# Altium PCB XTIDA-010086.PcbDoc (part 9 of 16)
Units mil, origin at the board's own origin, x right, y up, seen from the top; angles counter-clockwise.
Board outline 14763.78 x 8267.72 mil, 6 copper layers (Top Layer, GND Layer, Signal Layer 1, Signal Layer 2, Power Layer, Bottom Layer), stack 62 mil thick; 1933 components, 1002 nets, 4886 pads, 6482 vias.
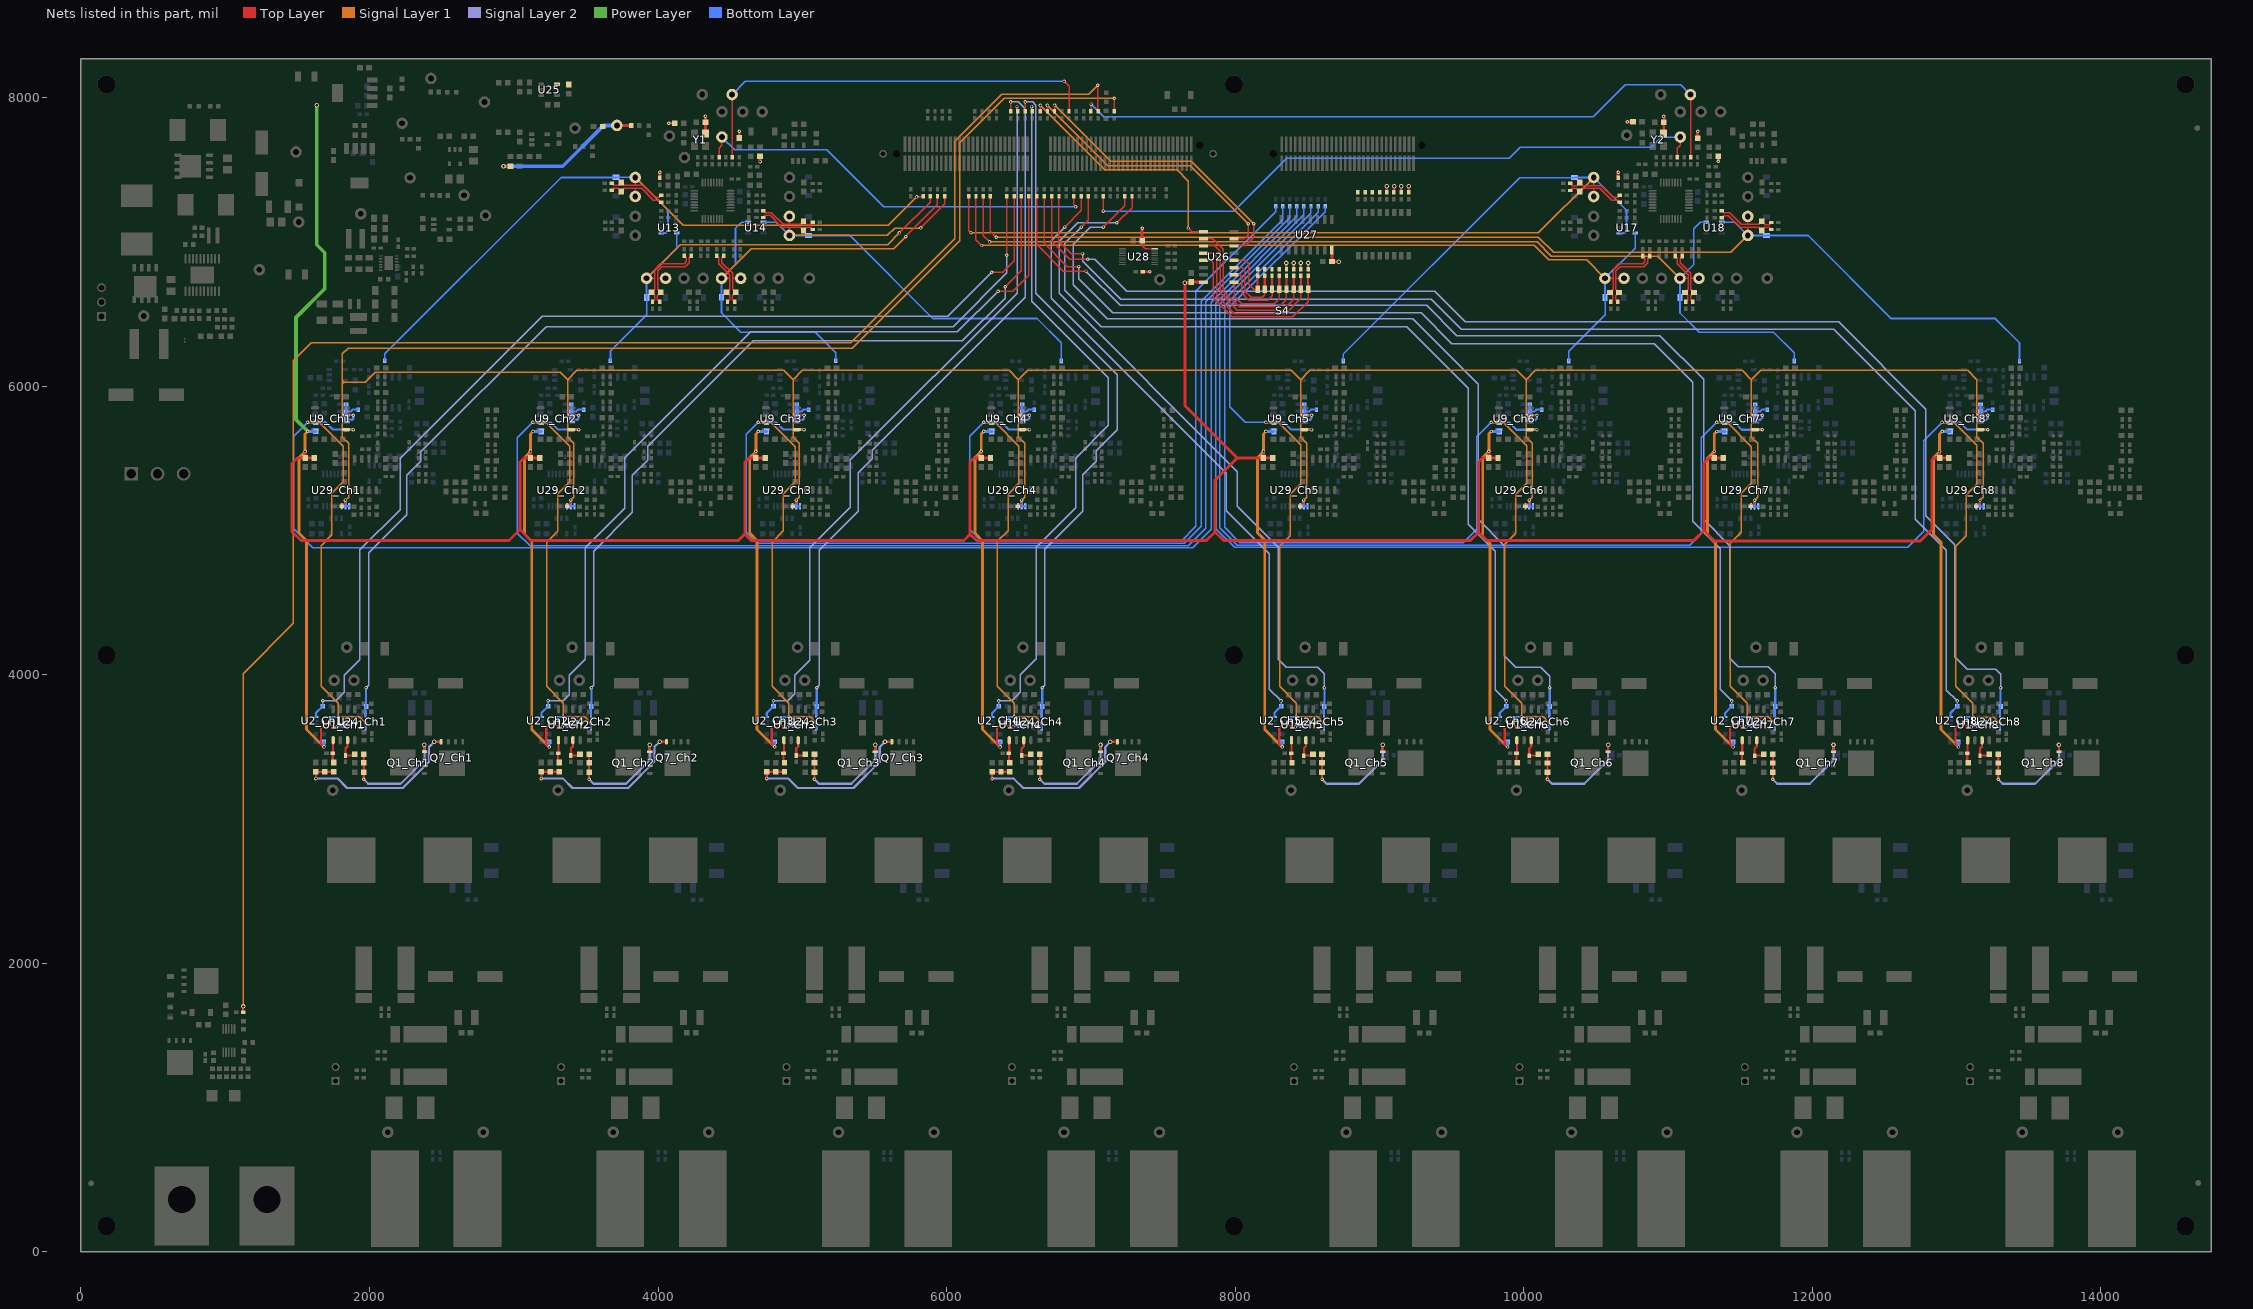
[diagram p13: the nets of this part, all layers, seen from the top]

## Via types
v1: diameter 32, hole 16, Top Layer to Bottom Layer, tented both sides, 4685 vias
v2: diameter 24, hole 12, Top Layer to Bottom Layer, tented both sides, 1013 vias
v3: diameter 32, hole 16, Top Layer to Bottom Layer, 728 vias
v4: diameter 19.68, hole 7.87, Top Layer to Bottom Layer, 40 vias
v5: diameter 214.57, hole 140, Top Layer to Bottom Layer, 16 vias

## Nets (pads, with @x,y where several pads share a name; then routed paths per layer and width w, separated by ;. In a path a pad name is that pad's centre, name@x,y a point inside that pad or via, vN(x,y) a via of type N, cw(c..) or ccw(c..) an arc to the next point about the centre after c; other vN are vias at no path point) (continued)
DIR: R58.1 R162_Ch1.1 R162_Ch2.1 R162_Ch3.1 R162_Ch4.1 R162_Ch5.1 R162_Ch6.1 R162_Ch7.1 R162_Ch8.1 U29_Ch1.9 U29_Ch1.10 U29_Ch1.11 U29_Ch2.9 U29_Ch2.10 U29_Ch2.11 U29_Ch3.9 U29_Ch3.10 U29_Ch3.11 U29_Ch4.9 U29_Ch4.10 U29_Ch4.11 U29_Ch5.9 U29_Ch5.10 U29_Ch5.11 U29_Ch6.9 U29_Ch6.10 U29_Ch6.11 U29_Ch7.9 U29_Ch7.10 U29_Ch7.11 U29_Ch8.9 U29_Ch8.10 U29_Ch8.11 | length 26555.4
  Top Layer w10: R58.1@7161,7903.32 7162,7904.32 v2(7162,7994)
  Top Layer w15: R162_Ch1.1@1808.39,5166.8 1833.98,5192.39 v2(1833.98,5209.98) ; R162_Ch2.1@3370.39,5166.72 3395.98,5192.31 v2(3395.98,5209.9) ; R162_Ch3.1@4932.39,5166.64 4957.98,5192.23 v2(4957.98,5209.82) ; R162_Ch4.1@6494.39,5166.56 6519.98,5192.15 v2(6519.98,5209.74) ; R162_Ch5.1@8450.09,5166.48 8475.68,5192.07 v2(8475.68,5209.66) ; R162_Ch6.1@10012.09,5166.4 10037.68,5191.99 v2(10037.68,5209.58) ; R162_Ch7.1@11574.09,5166.32 11599.68,5191.91 v2(11599.68,5209.5) ; R162_Ch8.1@13136.09,5166.24 13161.68,5191.84 v2(13161.68,5209.43)
  Signal Layer 1 w10: 1812.21,6016.21 1824,6028 1812.21,6039.79 ; v2(1833.98,5209.98) 1855,5231 1855,5603 1812.21,5645.79 1812.21,6028 ; v2(3395.98,5209.9) 3417,5230.92 3417,5602.92 3374.21,5645.71 3374.21,6044.79 ; v2(4957.98,5209.82) 4979,5230.84 4979,5602.84 4936.21,5645.63 4936.21,6044.71 ; v2(6519.98,5209.74) 6541,5230.76 6541,5602.76 6498.21,5645.55 6498.21,6044.63 ; v2(7162,7994) 6400,7994 6092,7686 6092,7007 5347,6262 1852,6262 1812.21,6222.21 1812.21,6028 ; v2(8475.68,5209.66) 8496.7,5230.69 8496.7,5602.69 8453.91,5645.47 8453.91,6044.55 ; v2(10037.68,5209.58) 10058.7,5230.61 10058.7,5602.61 10015.91,5645.39 10015.91,6044.47 ; v2(11599.68,5209.5) 11620.7,5230.53 11620.7,5602.53 11577.91,5645.32 11577.91,6044.39 ; v2(13161.68,5209.43) 13182.7,5230.45 13182.7,5602.45 13139.91,5645.24 13139.91,6044.32 13075.62,6108.61 11642.13,6108.61 11577.91,6044.39 ; 1812.21,6028 1972,6028 2040,6096 3323,6096 3374.21,6044.79 ; 3374.21,6044.79 3438.43,6109 4871.92,6109 4936.21,6044.71 ; 4936.21,6044.71 5000.43,6108.92 6433.92,6108.92 6498.21,6044.63 ; 6498.21,6044.63 6562.43,6108.84 8389.62,6108.84 8453.91,6044.55 ; 8453.91,6044.55 8518.13,6108.76 9951.62,6108.76 10015.91,6044.47 ; 10015.91,6044.47 10080.13,6108.69 11513.62,6108.69 11577.91,6044.39
  Bottom Layer w15: U29_Ch1.11@1808.39,5166.8 U29_Ch1.10@1833.98,5166.8 ; v2(1833.98,5209.98) U29_Ch1.10@1833.98,5166.8 ; U29_Ch1.9@1859.57,5166.8 U29_Ch1.10@1833.98,5166.8 ; U29_Ch2.11@3370.39,5166.72 U29_Ch2.10@3395.98,5166.72 ; v2(3395.98,5209.9) U29_Ch2.10@3395.98,5166.72 ; U29_Ch2.9@3421.57,5166.72 U29_Ch2.10@3395.98,5166.72 ; U29_Ch3.11@4932.39,5166.64 U29_Ch3.10@4957.98,5166.64 ; v2(4957.98,5209.82) U29_Ch3.10@4957.98,5166.64 ; U29_Ch3.9@4983.57,5166.64 U29_Ch3.10@4957.98,5166.64 ; U29_Ch4.11@6494.39,5166.56 U29_Ch4.10@6519.98,5166.56 ; v2(6519.98,5209.74) U29_Ch4.10@6519.98,5166.56 ; U29_Ch4.9@6545.57,5166.56 U29_Ch4.10@6519.98,5166.56 ; U29_Ch5.11@8450.09,5166.48 U29_Ch5.10@8475.68,5166.48 ; v2(8475.68,5209.66) U29_Ch5.10@8475.68,5166.48 ; U29_Ch5.9@8501.27,5166.48 U29_Ch5.10@8475.68,5166.48 ; U29_Ch6.11@10012.09,5166.4 U29_Ch6.10@10037.68,5166.4 ; v2(10037.68,5209.58) U29_Ch6.10@10037.68,5166.4 ; U29_Ch6.9@10063.27,5166.4 U29_Ch6.10@10037.68,5166.4 ; U29_Ch7.11@11574.09,5166.32 U29_Ch7.10@11599.68,5166.32 ; v2(11599.68,5209.5) U29_Ch7.10@11599.68,5166.32 ; U29_Ch7.9@11625.27,5166.32 U29_Ch7.10@11599.68,5166.32 ; U29_Ch8.11@13136.09,5166.24 U29_Ch8.10@13161.68,5166.24 ; v2(13161.68,5209.43) U29_Ch8.10@13161.68,5166.24 ; U29_Ch8.9@13187.27,5166.24 U29_Ch8.10@13161.68,5166.24
DOUT1: R105.2 R279.1 TP13.1 | length 2878.7
  Top Layer w10: R105.2@4423.11,7584.63 4423.11,7649.58 4443.11,7669.58 TP13.1@4443.11,7726.01 ; R279.1@6881.35,7315.88 6881.35,7255.65 v2(6894,7243)
  Bottom Layer w10: TP13.1@4443.11,7726.01 4531.13,7638 5170,7638 5565,7243 v2(6894,7243)
DOUT2: R136.2 R286.1 TP19.1 | length 4465
  Top Layer w10: R286.1@7084.35,7315.88 7084.35,7213.65 v2(7085,7213) ; R136.2@11064.82,7584.32 11064.82,7649.26 11084.82,7669.26 TP19.1@11084.82,7725.7
  Bottom Layer w10: v2(7085,7213) 7991,7213 8357,7579 9901,7579 9976,7654 10882,7654 10953.7,7725.7 TP19.1@11084.82,7725.7
DRDY1: R110.2 R278.1 TP15.1 | length 2996.1
  Top Layer w10: TP15.1@4513.49,8020.01 4515.11,8018.39 R110.2@4515.11,7584.63 ; v2(6814,8111) 6848.28,8076.72 R278.1@6848.28,7903.32
  Bottom Layer w10: TP15.1@4513.49,8020.01 4604.48,8111 v2(6814,8111)
DRDY2: R141.2 R283.1 TP21.1 | length 4798.1
  Top Layer w10: R283.1@6999.78,7903.32 7001,7904.54 v2(7001,7954) ; TP21.1@11155.19,8019.7 11156.82,8018.08 R141.2@11156.82,7584.32
  Bottom Layer w10: v2(7001,7954) 7089,7866 10482,7866 10704,8088 11086.89,8088 TP21.1@11155.19,8019.7
DVDD: C64.1 C85.1 C123.1 C124.1 C125.1 C163.1 R42.2 R69_Ch1.2 R69_Ch2.2 R69_Ch3.2 R69_Ch4.2 R69_Ch5.2 R69_Ch6.2 R69_Ch7.2 R69_Ch8.2 R98.2 R108.2 R109.2 R118.2 R129.2 R139.2 R140.2 R149.2 R172_Ch1.1 R172_Ch2.1 R172_Ch3.1 R172_Ch4.1 R172_Ch5.1 R172_Ch6.1 R172_Ch7.1 R172_Ch8.1 R173_Ch1.2 R173_Ch2.2 R173_Ch3.2 R173_Ch4.2 R173_Ch5.2 R173_Ch6.2 R173_Ch7.2 R173_Ch8.2 R174_Ch1.2 R174_Ch2.2 R174_Ch3.2 R174_Ch4.2 R174_Ch5.2 R174_Ch6.2 R174_Ch7.2 R174_Ch8.2 R179.1 R194.1 R203.2 R220_Ch1.1 R220_Ch2.1 R220_Ch3.1 R220_Ch4.1 R220_Ch5.1 R220_Ch6.1 R220_Ch7.1 R220_Ch8.1 R223.1 R224.1 R225.1 R226.1 R227.1 R228.1 R229.1 R230.1 R231.1 R232.1 R233.1 R234.1 R235.1 R236.1 R237.1 R238.1 TP25.1 U25.5 U26.16 U27.16 U28.16 Y1.4 Y2.4 | length 45171.5
  Top Layer w6: 7404.5,6951.51 U28.16@7442.41,6951.51
  Top Layer w10: C123.1@7360,7008.01 C123.1@7356.5,7008.01 7356.5,6973.14 7378.13,6951.51 7404.5,6951.51
  Top Layer w15: v2(1684.56,3499) 1664,3519.56 1664,3634 1689.82,3659.82 1724.18,3659.82 1746,3638 v2(1774.07,3638) ; v2(3246.56,3498.92) 3226,3519.48 3226,3633.92 3251.82,3659.74 3286.18,3659.74 3308,3637.92 v2(3336.07,3637.92) ; v2(4808.56,3498.84) 4788,3519.4 4788,3633.84 4813.82,3659.66 4848.18,3659.66 4870,3637.84 v2(4898.07,3637.84) ; v2(6370.56,3498.76) 6350,3519.32 6350,3633.76 6375.82,3659.58 6410.18,3659.58 6432,3637.76 v2(6460.07,3637.76) ; v2(8326.26,3498.69) 8305.7,3519.24 8305.7,3633.69 8331.52,3659.5 8365.88,3659.5 8387.7,3637.69 v2(8415.77,3637.69) ; R226.1@8354.35,6810.17 v1(8354.35,6853.23) ; R225.1@8405.35,6810.17 v1(8405.35,6853.23) ; R224.1@8454.35,6810.17 v1(8454.35,6853.23) ; R223.1@8505.35,6810.17 v1(8505.35,6853.23) ; R234.1@9050.86,7342.17 v1(9050.86,7385.23) ; R233.1@9101.86,7342.17 v1(9101.86,7385.23) ; R232.1@9150.86,7342.17 v1(9150.86,7385.23) ; R231.1@9201.86,7342.17 v1(9201.86,7385.23) ; v2(9888.26,3498.61) 9867.7,3519.17 9867.7,3633.61 9893.52,3659.43 9927.88,3659.43 9949.7,3637.61 v2(9977.77,3637.61) ; v2(11450.26,3498.53) 11429.7,3519.09 11429.7,3633.53 11455.52,3659.35 11489.88,3659.35 11511.7,3637.53 v2(11539.77,3637.53) ; v2(13012.26,3498.45) 12991.7,3519.01 12991.7,3633.45 13017.52,3659.27 13051.88,3659.27 13073.7,3637.45 v2(13101.77,3637.45)
  Top Layer w20: v2(1554,5547) R173_Ch1.2@1554,5501.99 ; R174_Ch1.2@1618,5501.99 R173_Ch1.2@1554,5501.99 ; v1(2929,7523.7) R194.1@2977.5,7523.7 ; v2(3116,5546.92) R173_Ch2.2@3116,5501.91 ; R174_Ch2.2@3180,5501.91 R173_Ch2.2@3116,5501.91 ; TP25.1@3715,7806 3813.44,7806 R179.1@3814.44,7805 ; R118.2@4012.11,7442.63 4012.53,7443.05 v2(4012.53,7482.63) ; v2(4073.77,7821.21) R98.2@4115.29,7821.21 ; Y1.4@4328.52,7749.32 4328.52,7828.92 C64.1@4328.61,7829.01 v2(4328.61,7870.54) ; R108.2@4563.11,7718.51 v2(4563.11,7765.01) ; v2(4678,5546.84) R173_Ch3.2@4678,5501.83 ; R109.2@4706.61,7592.01 4707,7591.62 v2(4707,7555.7) ; R174_Ch3.2@4742,5501.83 R173_Ch3.2@4678,5501.83 ; v2(6240,5546.76) R173_Ch4.2@6240,5501.76 ; R174_Ch4.2@6304,5501.76 R173_Ch4.2@6240,5501.76 ; v2(7355,7093) 7355,7013.01 C123.1@7360,7008.01 ; R42.2@7358.62,6792.01 v2(7408,6792.01) ; C124.1@7696.28,6720.7 7698.28,6718.7 7696.58,6717 v1(7651,6717) 7651,5865 8014.32,5501.68 ; C124.1@7700.28,6720.7 U26.16@7779.49,6720.7 ; v2(8195.7,5546.69) R173_Ch5.2@8195.7,5501.68 ; R174_Ch5.2@8259.7,5501.68 R173_Ch5.2@8195.7,5501.68 ; C125.1@8670.2,6859.46 8672.2,6861.46 v1(8717.7,6861.46) ; C125.1@8670.2,6863.46 U27.16@8670.2,6942.67 ; v2(9757.7,5546.61) R173_Ch6.2@9757.7,5501.6 ; R174_Ch6.2@9821.7,5501.6 R173_Ch6.2@9757.7,5501.6 ; R149.2@10653.82,7442.32 10654.23,7442.73 v2(10654.23,7482.32) ; v2(10716.89,7831) R129.2@10756.5,7831 R129.2@10756.99,7830.52 ; Y2.4@10970.22,7749 10970.22,7828.6 10970.7,7829.09 v2(10970.7,7868.7) ; R139.2@11204.82,7718.19 v2(11204.82,7764.7) ; v2(11319.7,5546.53) R173_Ch7.2@11319.7,5501.52 ; v2(11348.31,7557.32) R140.2@11348.31,7591.7 ; R174_Ch7.2@11383.7,5501.52 R173_Ch7.2@11319.7,5501.52 ; v2(12881.7,5546.45) R173_Ch8.2@12881.7,5501.44 ; R174_Ch8.2@12945.7,5501.44 R173_Ch8.2@12881.7,5501.44 ; R173_Ch1.2@1554,5501.99 1501.99,5501.99 1464,5464 1464,4990 1525,4929 2967,4929 3043,5005 ; 3043,5005 3043,5473 3071.91,5501.91 R173_Ch2.2@3116,5501.91 ; 3043,5005 3118,4930 4556,4930 4601,4975 ; 4601,4975 4601,5470.46 4632.37,5501.83 R173_Ch3.2@4678,5501.83 ; 4601,4975 4646,4930 6120,4930 6163,4973 ; 6163,4973 6163,5473 6191.76,5501.76 R173_Ch4.2@6240,5501.76 ; 6163,4973 6207,4929 7800,4929 7860,4989 ; 7860,4989 7860,5347.35 8014.32,5501.68 ; 7860,4989 7918,4931 9631,4931 9686,4986 ; 8014.32,5501.68 R173_Ch5.2@8195.7,5501.68 ; 9686,4986 9686,5474 9713.6,5501.6 R173_Ch6.2@9757.7,5501.6 ; 9686,4986 9741,4931 11181,4931 11248,4998 ; 11248,4998 11248,5465 11284.52,5501.52 R173_Ch7.2@11319.7,5501.52 ; 11248,4998 11320,4926 12748,4926 12827,5005 12827,5486 12842.44,5501.44 R173_Ch8.2@12881.7,5501.44
  Power Layer w25: v2(1572.01,5686.01) 1491,5767.02 1491,6474.81 1691,6674.81 1691,6923 1634.22,6979.78 v1(1634.22,7945.22)
  Signal Layer 1 w20: v2(1572.01,5686.01) 1554,5668 v2(1554,5547) 1512,5505 1512,4981 1563,4930 1563,3620.56 v2(1684.56,3499) ; v2@3134.01,5685.93 v2(3133.56,5685.48) 3116,5667.92 v2(3116,5546.92) 3074,5504.92 3074,4974 3125,4923 3125,3620.48 v2(3246.56,3498.92) ; v2@4696.01,5685.85 v2(4695.56,5685.4) 4678,5667.84 v2(4678,5546.84) 4636,5504.84 4636,4980 4687,4929 4687,3620.4 v2(4808.56,3498.84) ; v2@6258.01,5685.77 v2(6257.56,5685.32) 6240,5667.76 v2(6240,5546.76) 6198,5504.76 6198,4978 6249,4927 6249,3620.32 v2(6370.56,3498.76) ; v2@8213.71,5685.69 v2(8213.26,5685.24) 8195.7,5667.69 v2(8195.7,5546.69) 8153.7,5504.69 8153.7,4983.6 8204.7,4932.6 8204.7,3620.24 v2(8326.26,3498.69) ; v2@9775.71,5685.61 v2(9775.26,5685.17) 9757.7,5667.61 v2(9757.7,5546.61) 9715.7,5504.61 9715.7,4958.3 9766.7,4907.3 9766.7,3620.17 v2(9888.26,3498.61) ; v2@11337.71,5685.54 v2(11337.26,5685.09) 11319.7,5667.53 v2(11319.7,5546.53) 11274,5500.83 11274,4972 11328.7,4917.3 11328.7,3620.09 v2(11450.26,3498.53) ; v2(12899.71,5685.46) 12881.7,5667.45 v2(12881.7,5546.45) 12839.7,5504.45 12839.7,4969.3 12890.7,4918.3 12890.7,3620.01 v2(13012.26,3498.45)
  Bottom Layer w20: v2(1572.01,5686.01) R69_Ch1.2@1628,5686.01 ; v2(1684.56,3499) R172_Ch1.1@1684.56,3534.69 ; v2(1774.07,3638) 1783.13,3647.06 R220_Ch1.1@1822,3647.06 ; v2(3133.56,5685.48) R69_Ch2.2@3189.55,5685.48 ; v2(3246.56,3498.92) R172_Ch2.1@3246.56,3534.61 ; v2(3336.07,3637.92) 3345.13,3646.98 R220_Ch2.1@3384,3646.98 ; v2(4695.56,5685.4) R69_Ch3.2@4751.55,5685.4 ; v2(4808.56,3498.84) R172_Ch3.1@4808.56,3534.53 ; v2(4898.07,3637.84) 4907.13,3646.9 R220_Ch3.1@4946,3646.9 ; v2(6257.56,5685.32) R69_Ch4.2@6313.55,5685.32 ; v2(6370.56,3498.76) R172_Ch4.1@6370.56,3534.45 ; v2(6460.07,3637.76) 6469.13,3646.82 R220_Ch4.1@6508,3646.82 ; v2(8213.26,5685.24) R69_Ch5.2@8269.25,5685.24 ; v2(8326.26,3498.69) R172_Ch5.1@8326.26,3534.37 ; v2(8415.77,3637.69) 8424.83,3646.75 R220_Ch5.1@8463.7,3646.75 ; v2(9775.26,5685.17) R69_Ch6.2@9831.25,5685.17 ; v2(9888.26,3498.61) R172_Ch6.1@9888.26,3534.29 ; v2(9977.77,3637.61) 9986.83,3646.67 R220_Ch6.1@10025.7,3646.67 ; v2(11337.26,5685.09) R69_Ch7.2@11393.25,5685.09 ; v2(11450.26,3498.53) R172_Ch7.1@11450.26,3534.21 ; v2(11539.77,3637.53) 11548.83,3646.59 R220_Ch7.1@11587.7,3646.59 ; v2(12899.71,5685.46) R69_Ch8.2@12955.7,5685.46 ; v2(13012.26,3498.45) R172_Ch8.1@13012.26,3534.13 ; v2(13101.77,3637.45) 13110.83,3646.51 R220_Ch8.1@13149.7,3646.51
  Bottom Layer w25: v1(2929,7523.7) 3339.7,7523.7 3622,7806 TP25.1@3715,7806
EN_A: R293.2 U26.9 | length 1723.8
  Top Layer w10: R293.2@6650,7903.54 v2(6650,7945) ; v2(7675,7095.51) 7699.81,7070.7 U26.9@7779.49,7070.7
  Signal Layer 1 w10: v2(6650,7945) 7097,7498 7598,7498 7675,7421 v2(7675,7095.51)
EN_B: R294.2 U26.7 | length 1957.8
  Top Layer w10: R294.2@6699,7903.54 v2(6699,7945) ; U26.7@7992.09,7020.7 8061.7,7020.7 8090,7049 v2(8090,7125)
  Signal Layer 1 w10: v2(6699,7945) 7117,7527 7688,7527 v2(8090,7125)
EN_C: R295.2 U26.6 | length 2018
  Top Layer w10: R295.2@6748,7903.54 v2(6748,7945) ; U26.6@7992.09,6970.7 8068.73,6970.7 8129,7030.97 v2(8129,7125)
  Signal Layer 1 w10: v2(6748,7945) 7136,7557 7695,7557 8127,7125 v2(8129,7125)
EN_CH1: R226.2 S4.4 U26.10 | length 1127.1
  Top Layer w10: U26.10@7779.06,7021.12 U26.10@7779.49,7020.7 7844.79,7020.7 7917.36,6948.12 7917.36,6657.81 8026.63,6548.55 8305.27,6548.55 8355.35,6598.62 S4.4@8355.35,6670.55
  Top Layer w15: S4.4@8355.35,6670.55 R226.2@8355.35,6762.92
EN_CH2: R225.2 S4.3 U26.11 | length 1174
  Top Layer w10: U26.11@7779.49,6970.7 7779.06,6971.12 7858.36,6971.12 7894.79,6934.7 7894.79,6645.39 8014.21,6525.97 8330.69,6525.97 8405.35,6600.62 S4.3@8405.35,6670.55
  Top Layer w15: S4.3@8405.35,6670.55 R225.2@8405.35,6762.92
EN_CH3: R224.2 S4.2 U26.12 | length 1207.8
  Top Layer w10: U26.12@7778.61,6919.83 U26.12@7779.49,6920.7 7845.79,6920.7 7871.79,6894.7 7871.79,6625.39 7995.18,6502 8349.72,6502 8455.35,6607.62 S4.2@8455.35,6670.55
  Top Layer w15: R224.2@8454.35,6762.92 8455.35,6761.92 S4.2@8455.35,6670.55
EN_CH4: R223.2 S4.1 U26.13 | length 1253.1
  Top Layer w10: U26.13@7779.49,6870.7 7779.06,6871.12 7833.36,6871.12 7848.79,6855.7 7848.79,6611.32 7980.11,6480 8399.72,6480 8505.35,6585.62 S4.1@8505.35,6670.55
  Top Layer w15: S4.1@8505.35,6670.55 R223.2@8505.35,6762.92
EN_CH5: R227.2 S4.5 U26.1 | length 604.4
  Top Layer w10: U26.1@7992.09,6720.7 7992.09,6624.09 8045.49,6570.69 8271.41,6570.69 8305.35,6604.62 S4.5@8305.35,6670.55
  Top Layer w15: S4.5@8305.35,6670.55 R227.2@8305.35,6762.92
EN_CH6: R228.2 S4.6 U26.2 | length 550.7
  Top Layer w10: U26.2@7992.09,6770.7 8032.79,6770.7 8045.79,6757.7 8045.79,6645.84 8095.65,6595.97 8225.69,6595.97 8255.35,6625.62 S4.6@8255.35,6670.55
  Top Layer w15: S4.6@8255.35,6670.55 R228.2@8255.35,6762.92
EN_CH7: R229.2 S4.7 U26.3 | length 523.4
  Top Layer w10: U26.3@7992.09,6820.7 8049.79,6820.7 8067.79,6802.7 8067.79,6655.84 8109.65,6613.97 8187.48,6613.97 8205.35,6631.84 S4.7@8205.35,6670.55
  Top Layer w15: S4.7@8205.35,6670.55 R229.2@8205.35,6762.92
EN_CH8: R230.2 S4.8 U26.4 | length 421.1
  Top Layer w10: U26.4@7992.09,6870.7 8068.79,6870.7 8092.79,6846.7 8092.79,6705.76 8128,6670.55 S4.8@8155.35,6670.55
  Top Layer w15: S4.8@8155.35,6670.55 R230.2@8155.35,6762.92
EPWM_A1: R216_Ch1.2 R261.1 U24_Ch1.6 | length 7091
  Top Layer w10: v2@6417.68,6906 R261.1@6417.68,7315.72
  Signal Layer 2 w10: v2(1976.61,3909.61) 1994,3927 1994,4844 2258,5108 2258,5382.56 2356,5480.56 2356,5543 3225,6412 6045,6412 6417.68,6784.68 v2@6417.68,6906
  Bottom Layer w15: U24_Ch1.6@1973.18,3717.62 1973.18,3775.69 R216_Ch1.2@1976.61,3779.11 v2(1976.61,3909.61)
  other v2: 6417.67,6905.99
EPWM_A2: R216_Ch2.2 R265.1 U24_Ch2.6 | length 5682.8
  Top Layer w10: v2@6406,6688.2 6518.35,6800.55 R265.1@6518.35,7315.88
  Signal Layer 2 w10: v2(3538.61,3909.53) 3555,3925.92 3555,4856.1 3823,5124.1 3823,5381 3929,5487 3929,5582 4661,6314 6110,6314 6405.99,6609.99 v2(6405.99,6688.19)
  Bottom Layer w15: U24_Ch2.6@3535.18,3717.54 3535.18,3775.61 R216_Ch2.2@3538.61,3779.04 v2(3538.61,3909.53)
EPWM_A3: R216_Ch3.2 R262.1 U24_Ch3.6 | length 4989.6
  Top Layer w10: R262.1@6443.89,7903.54 6443.61,7903.82 6444,7904.21 v2(6444,7969)
  Signal Layer 2 w10: v2(5100.61,3909.45) 5118,3926.84 5118,4863 5386,5131 5386,5398 5485,5497 5485,5555 6544,6614 6544,7743 6544,7923 6498,7969 v2(6444,7969)
  Bottom Layer w15: U24_Ch3.6@5097.18,3717.46 5097.18,3775.53 R216_Ch3.2@5100.61,3778.96 v2(5100.61,3909.45)
EPWM_A4: R216_Ch4.2 R266.1 U24_Ch4.6 | length 4827
  Top Layer w10: R266.1@6544.56,7903.39 R266.1@6544.42,7903.54 6544.27,7903.68 6544.67,7904.07 v2(6544.67,7968.86)
  Signal Layer 2 w10: v2(6544.67,7968.86) 6596,7968.86 6617.14,7947.72 6617.14,6643.86 7181,6080 7181,5697 7036,5552 7036,5478 6942,5384 6942,5131 6680,4869 6680,3926.76 v2(6662.61,3909.37)
  Bottom Layer w15: U24_Ch4.6@6659.18,3717.38 6659.18,3775.45 R216_Ch4.2@6662.61,3778.88 v2(6662.61,3909.37)
EPWM_A5: R216_Ch5.2 R270.2 U24_Ch5.6 | length 4856.2
  Top Layer w10: v2(7179.74,7132) 7285,7237.26 R270.2@7285,7316.38
  Signal Layer 2 w10: v2(7179.74,7132) 6910,7132 6780,7002 6780,6642 8016,5406 8016,5168 8300,4884 8300,4107 8355,4052 8572,4052 8618.31,4005.69 v2(8618.31,3909.29)
  Bottom Layer w15: U24_Ch5.6@8614.88,3717.3 8614.88,3775.37 R216_Ch5.2@8618.31,3778.8 v2(8618.31,3909.29)
EPWM_A6: R216_Ch6.2 R272.2 U24_Ch6.6 | length 6512.4
  Top Layer w10: v2@7086,7101 7235,7250 R272.2@7235,7316.38
  Signal Layer 2 w10: v2(7086,7102) 6997,7102 6877,6982 6877,6701 7113,6465 9232,6465 9684,6013 9684,5076 9866,4894 9866,4130.76 9945.76,4051 10118,4051 10180.31,3988.69 v2(10180.31,3909.21)
  Bottom Layer w15: U24_Ch6.6@10176.88,3717.23 10176.88,3775.29 R216_Ch6.2@10180.31,3778.72 v2(10180.31,3909.21)
EPWM_A7: R216_Ch7.2 R269.1 U24_Ch7.6 | length 8001.2
  Top Layer w10: R269.1@6624.68,7315.88 6624.68,6981.32 6809,6797 v2(6966,6797)
  Signal Layer 2 w10: v2(6966,6797) 7204.39,6558.61 9326.39,6558.61 9537,6348 10943.7,6348 11246,6045.7 11246,5078 11429,4895 11429,4112 11485,4056 11693.58,4056 11742.31,4007.27 v2(11742.31,3909.14)
  Bottom Layer w15: U24_Ch7.6@11738.88,3717.15 11738.88,3775.21 R216_Ch7.2@11742.31,3778.64 v2(11742.31,3909.14)
EPWM_A8: R216_Ch8.2 R273.1 U24_Ch8.6 | length 9306.9
  Top Layer w10: R273.1@6727.35,7315.88 6727.35,7004.15 6852.5,6879 v2(6978,6879)
  Signal Layer 2 w10: v2(6978,6879) 7026.5,6879 7249.5,6656 9384,6656 9595,6445 12182.7,6445 12787,5840.7 12787,5101 12988,4900 12988,4123 13075,4036 13270,4036 13304.31,4001.69 v2(13304.31,3909.06)
  Bottom Layer w15: U24_Ch8.6@13300.88,3717.07 13300.88,3775.14 R216_Ch8.2@13304.31,3778.56 v2(13304.31,3909.06)
EPWM_B1: R217_Ch1.2 R263.1 U2_Ch1.6 | length 7357.8
  Top Layer w10: v2(6311.99,6788.99) 6389.99,6788.99 6468.01,6867.01 R263.1@6468.01,7315.88
  Signal Layer 2 w10: v2(1676.27,3818.35) 1766.11,3818.35 1826,3878.24 1826,3996 1933,4103 1933,4864 2212,5143 2212,5499 3197,6484 6007,6484 v2(6311.99,6788.99)
  Bottom Layer w10: R217_Ch1.2@1676.27,3781.39 v2(1676.27,3818.35)
  Bottom Layer w15: U2_Ch1.6@1629.71,3706.59 1629.71,3734.83 R217_Ch1.2@1676.27,3781.39
EPWM_B2: R217_Ch2.2 R267.1 U2_Ch2.6 | length 5975.7
  Top Layer w10: v2@6364,6657 6458,6657 6568.68,6767.68 R267.1@6568.68,7315.88
  Signal Layer 2 w10: v2(3238.27,3818.27) 3343.55,3818.27 3386,3860.72 3386,3997 3497,4108 3497,4880 3771,5154 3771,5504 4642,6375 6075,6375 v2(6357,6657) v2@6364,6657
  Bottom Layer w10: v2(3238.27,3818.27) R217_Ch2.2@3238.27,3781.31 R217_Ch2.2@3243.44,3776.15
  Bottom Layer w15: U2_Ch2.6@3191.71,3706.51 3191.71,3734.75 R217_Ch2.2@3238.27,3781.31
EPWM_B3: R217_Ch3.2 R264.1 U2_Ch3.6 | length 5049.7
  Top Layer w10: v2(6488,7937) 6488,7909.95 6494,7903.95 6493.87,7903.82 R264.1@6494.15,7903.54
  Signal Layer 2 w10: v2(4800.27,3818.19) 4898.24,3818.19 4948,3867.95 4948,3996 5053,4101 5053,4880 5332,5159 5332,5488 6488,6644 v2(6488,7937)
  Bottom Layer w10: v2(4800.27,3818.19) R217_Ch3.2@4800.27,3781.23 R217_Ch3.2@4805.44,3776.07
  Bottom Layer w15: U2_Ch3.6@4753.71,3706.43 4753.71,3734.67 R217_Ch3.2@4800.27,3781.23
EPWM_B4: R217_Ch4.2 R268.1 U2_Ch4.6 | length 4881
  Top Layer w10: v2(6588.67,7936.86) 6588.67,7909.81 6594.67,7903.81 6594.54,7903.68 R268.1@6594.68,7903.54 R268.1@6594.82,7903.39
  Signal Layer 2 w10: v2(6362.27,3818.11) 6451.35,3818.11 6510,3876.76 6510,4000 6621,4111 6621,4884 6894.54,5157.54 6894.54,5499.93 7122,5727.39 7122,6056 6588.67,6589.33 v2(6588.67,7936.86)
  Bottom Layer w10: v2(6362.27,3818.11) R217_Ch4.2@6362.27,3781.15 R217_Ch4.2@6367.44,3775.99
  Bottom Layer w15: U2_Ch4.6@6315.71,3706.35 6315.71,3734.59 R217_Ch4.2@6362.27,3781.15
EPWM_B5: R217_Ch5.2 R281.1 U2_Ch5.6 | length 4382.9
  Top Layer w10: v2(6818,7102) 6932.68,7216.68 R281.1@6932.68,7315.88
  Signal Layer 2 w10: v2(6818,7102) 6724,7008 6724,6608 7937,5395 7937,5137 8236,4838 8236,3900.01 v2(8317.97,3818.04)
  Bottom Layer w10: v2(8317.97,3818.04) R217_Ch5.2@8317.97,3781.08 R217_Ch5.2@8323.14,3775.91
  Bottom Layer w15: U2_Ch5.6@8271.41,3706.28 8271.41,3734.51 R217_Ch5.2@8317.97,3781.08
EPWM_B6: R217_Ch6.2 R276.2 U2_Ch6.6 | length 6204.3
  Top Layer w10: v2@6934,7101 6983,7150 R276.2@6983,7315.88
  Signal Layer 2 w10: v2(6933,7102) 6819,6988 6819,6665 7073,6411 9188,6411 9614,5985 9614,5044 9803.38,4854.62 9803.38,3894.55 v2(9879.97,3817.96)
  Bottom Layer w10: R217_Ch6.2@9879.97,3781 v2(9879.97,3817.96)
  Bottom Layer w15: U2_Ch6.6@9833.41,3706.2 9833.41,3734.43 R217_Ch6.2@9879.97,3781
EPWM_B7: R217_Ch7.2 R271.1 U2_Ch7.6 | length 7728.8
  Top Layer w10: R271.1@6676.01,7315.88 6676.01,6989.83 6837.85,6828 v2@6915,6828
  Signal Layer 2 w10: v2(6914.99,6827.99) 6914.99,6743.01 7151,6507 9288.7,6507 9501.7,6294 10903,6294 11170,6027 11170,5063 11362,4871 11362,3897.85 v2(11441.97,3817.88)
  Bottom Layer w10: v2(11441.97,3817.88) R217_Ch7.2@11441.97,3780.92 R217_Ch7.2@11447.14,3775.75
  Bottom Layer w15: U2_Ch7.6@11395.41,3706.12 11395.41,3734.35 R217_Ch7.2@11441.97,3780.92
EPWM_B8: R217_Ch8.2 R275.1 U2_Ch8.6 | length 9033.4
  Top Layer w10: R275.1@6778.68,7315.88 6778.68,7004.32 6865,6918 v2(6942.28,6918)
  Signal Layer 2 w10: v2(6942.28,6918) 6942.28,6865.72 7207,6601 9358,6601 9566,6393 12149,6393 12714,5828 12714,5078 12928.61,4863.39 12928.61,3893.16 v2(13003.97,3817.8)
  Bottom Layer w10: v2(13003.97,3817.8) R217_Ch8.2@13003.97,3780.84 R217_Ch8.2@13009.14,3775.67
  Bottom Layer w15: U2_Ch8.6@12957.41,3706.04 12957.41,3734.28 R217_Ch8.2@13003.97,3780.84
FAULT: R86.2 R289.1 | length 11605.2
  Top Layer w10: v2(7048,8085) 7048,7907.32 R289.1@7052,7903.32
  Top Layer w15: R86.2@1124.62,1659 v1(1124.62,1700.62)
  Signal Layer 1 w10: v1(1124.62,1700.62) 1124.62,4006.62 1473,4355 1473,6177 1596,6300 5334,6300 6056,7022 6056,7695 6383,8022 6985,8022 v2(7048,8085)
H-Drive_Ch1: D3_Ch1.1 R11_Ch1.2 U1_Ch1.7 | length 179.1
  Top Layer w15: U1_Ch1.7@1848.37,3545.79 1848.37,3502.37 1834.11,3488.11 D3_Ch1.1@1834.11,3439.77 1887.85,3439.77 R11_Ch1.2@1897.37,3449.29
H-Drive_Ch2: D3_Ch2.1 R11_Ch2.2 U1_Ch2.7 | length 179.1
  Top Layer w15: U1_Ch2.7@3410.37,3545.71 3410.37,3502.29 3396.11,3488.04 D3_Ch2.1@3396.11,3439.69 3449.85,3439.69 R11_Ch2.2@3459.37,3449.21
H-Drive_Ch3: D3_Ch3.1 R11_Ch3.2 U1_Ch3.7 | length 179.1
  Top Layer w15: U1_Ch3.7@4972.37,3545.63 4972.37,3502.21 4958.11,3487.96 D3_Ch3.1@4958.11,3439.61 5011.85,3439.61 R11_Ch3.2@5021.37,3449.13
H-Drive_Ch4: D3_Ch4.1 R11_Ch4.2 U1_Ch4.7 | length 179.1
  Top Layer w15: U1_Ch4.7@6534.37,3545.55 6534.37,3502.14 6520.11,3487.88 D3_Ch4.1@6520.11,3439.53 6573.85,3439.53 R11_Ch4.2@6583.37,3449.05
H-Drive_Ch5: D3_Ch5.1 R11_Ch5.2 U1_Ch5.7 | length 179.1
  Top Layer w15: U1_Ch5.7@8490.07,3545.47 8490.07,3502.06 8475.81,3487.8 D3_Ch5.1@8475.81,3439.45 8529.55,3439.45 R11_Ch5.2@8539.07,3448.97
H-Drive_Ch6: D3_Ch6.1 R11_Ch6.2 U1_Ch6.7 | length 179.1
  Top Layer w15: U1_Ch6.7@10052.07,3545.39 10052.07,3501.98 10037.81,3487.72 D3_Ch6.1@10037.81,3439.37 10091.55,3439.37 R11_Ch6.2@10101.07,3448.9
H-Drive_Ch7: D3_Ch7.1 R11_Ch7.2 U1_Ch7.7 | length 179.1
  Top Layer w15: U1_Ch7.7@11614.07,3545.31 11614.07,3501.9 11599.81,3487.64 D3_Ch7.1@11599.81,3439.3 11653.55,3439.3 R11_Ch7.2@11663.07,3448.82
H-Drive_Ch8: D3_Ch8.1 R11_Ch8.2 U1_Ch8.7 | length 179.1
  Top Layer w15: U1_Ch8.7@13176.07,3545.23 13176.07,3501.82 13161.81,3487.56 D3_Ch8.1@13161.81,3439.22 13215.55,3439.22 R11_Ch8.2@13225.07,3448.74
HDrive_Ch1: Q1_Ch1.4 R11_Ch1.1 R18_Ch1.2 R19_Ch1.2 | length 829
  Top Layer w15: v2(1960.36,3275.11) R18_Ch1.2@1960.36,3323.07 R19_Ch1.2@1960.36,3388.42 R11_Ch1.1@1960.36,3449.29 ; Q1_Ch1.4@2381,3466 v1(2381,3513.95)
  Signal Layer 2 w15: v2(1960.36,3275.11) 1991.48,3244 2216,3244 2381,3409 v1(2381,3513.95)
HDrive_Ch2: Q1_Ch2.4 R11_Ch2.1 R18_Ch2.2 R19_Ch2.2 | length 829
  Top Layer w15: v2(3522.36,3275.04) R18_Ch2.2@3522.36,3322.99 R19_Ch2.2@3522.36,3388.34 R11_Ch2.1@3522.36,3449.21 ; Q1_Ch2.4@3943,3465.92 v1(3943,3513.88)
  Signal Layer 2 w15: v2(3522.36,3275.04) 3553.48,3243.92 3778,3243.92 3943,3408.92 v1(3943,3513.88)
HDrive_Ch3: Q1_Ch3.4 R11_Ch3.1 R18_Ch3.2 R19_Ch3.2 | length 829
  Top Layer w15: v2(5084.36,3274.96) R18_Ch3.2@5084.36,3322.91 R19_Ch3.2@5084.36,3388.26 R11_Ch3.1@5084.36,3449.13 ; Q1_Ch3.4@5505,3465.84 v1(5505,3513.8)
  Signal Layer 2 w15: v2(5084.36,3274.96) 5115.48,3243.84 5340,3243.84 5505,3408.84 v1(5505,3513.8)
HDrive_Ch4: Q1_Ch4.4 R11_Ch4.1 R18_Ch4.2 R19_Ch4.2 | length 829
  Top Layer w15: v2(6646.36,3274.88) R18_Ch4.2@6646.36,3322.83 R19_Ch4.2@6646.36,3388.18 R11_Ch4.1@6646.36,3449.05 ; Q1_Ch4.4@7067,3465.76 v1(7067,3513.72)
  Signal Layer 2 w15: v2(6646.36,3274.88) 6677.48,3243.76 6902,3243.76 7067,3408.76 v1(7067,3513.72)
HDrive_Ch5: Q1_Ch5.4 R11_Ch5.1 R18_Ch5.2 R19_Ch5.2 | length 829
  Top Layer w15: v2(8602.06,3274.8) R18_Ch5.2@8602.06,3322.75 R19_Ch5.2@8602.06,3388.1 R11_Ch5.1@8602.06,3448.97 ; Q1_Ch5.4@9022.7,3465.69 v1(9022.7,3513.64)
  Signal Layer 2 w15: v2(8602.06,3274.8) 8633.18,3243.69 8857.7,3243.69 9022.7,3408.69 v1(9022.7,3513.64)
HDrive_Ch6: Q1_Ch6.4 R11_Ch6.1 R18_Ch6.2 R19_Ch6.2 | length 829
  Top Layer w15: v2(10164.06,3274.72) R18_Ch6.2@10164.06,3322.68 R19_Ch6.2@10164.06,3388.02 R11_Ch6.1@10164.06,3448.9 ; Q1_Ch6.4@10584.7,3465.61 v1(10584.7,3513.56)
  Signal Layer 2 w15: v2(10164.06,3274.72) 10195.18,3243.61 10419.7,3243.61 10584.7,3408.61 v1(10584.7,3513.56)
HDrive_Ch7: Q1_Ch7.4 R11_Ch7.1 R18_Ch7.2 R19_Ch7.2 | length 829
  Top Layer w15: v2(11726.06,3274.64) R18_Ch7.2@11726.06,3322.6 R19_Ch7.2@11726.06,3387.94 R11_Ch7.1@11726.06,3448.82 ; Q1_Ch7.4@12146.7,3465.53 v1(12146.7,3513.48)
  Signal Layer 2 w15: v2(11726.06,3274.64) 11757.18,3243.53 11981.7,3243.53 12146.7,3408.53 v1(12146.7,3513.48)
HDrive_Ch8: Q1_Ch8.4 R11_Ch8.1 R18_Ch8.2 R19_Ch8.2 | length 829
  Top Layer w15: v2(13288.06,3274.56) R18_Ch8.2@13288.06,3322.52 R19_Ch8.2@13288.06,3387.86 R11_Ch8.1@13288.06,3448.74 ; Q1_Ch8.4@13708.7,3465.45 v1(13708.7,3513.4)
  Signal Layer 2 w15: v2(13288.06,3274.56) 13319.18,3243.45 13543.7,3243.45 13708.7,3408.45 v1(13708.7,3513.4)
HTV_2.5V_Ch1: C46_Ch1.2 R61_Ch1.1 R62_Ch1.2 R192_Ch1.2 U9_Ch1.3 | length 324.3
  Top Layer w15: U9_Ch1.3@1838.28,5798.55 v2(1887.85,5798.55)
  Bottom Layer w15: R61_Ch1.1@1837.62,5873.7 R62_Ch1.2@1837.62,5824.7 ; v2(1887.85,5798.55) 1887.85,5773.06 1881.38,5766.59 C46_Ch1.2@1838.28,5766.59 1838.28,5824.04 R62_Ch1.2@1837.62,5824.7 ; R192_Ch1.2@1922,5837.38 1884.38,5837.38 1871.7,5824.7 R62_Ch1.2@1837.62,5824.7
HTV_2.5V_Ch2: C46_Ch2.2 R61_Ch2.1 R62_Ch2.2 R192_Ch2.2 U9_Ch2.3 | length 323.2
  Top Layer w15: U9_Ch2.3@3400.28,5798.47 v2(3449.85,5798.47)
  Bottom Layer w15: R61_Ch2.1@3399.62,5873.62 R62_Ch2.2@3399.62,5824.62 ; v2(3449.85,5798.47) 3449.85,5774.85 3441.51,5766.51 C46_Ch2.2@3400.28,5766.51 3400.28,5823.96 R62_Ch2.2@3399.62,5824.62 ; R192_Ch2.2@3484,5837.3 3446.38,5837.3 3433.7,5824.62 R62_Ch2.2@3399.62,5824.62
HTV_2.5V_Ch3: C46_Ch3.2 R61_Ch3.1 R62_Ch3.2 R192_Ch3.2 U9_Ch3.3 | length 324.3
  Top Layer w15: U9_Ch3.3@4962.28,5798.39 v2(5011.85,5798.39)
  Bottom Layer w15: R61_Ch3.1@4961.62,5873.54 R62_Ch3.2@4961.62,5824.54 ; v2(5011.85,5798.39) 5011.85,5772.85 5005.43,5766.43 C46_Ch3.2@4962.28,5766.43 4962.28,5823.88 R62_Ch3.2@4961.62,5824.54 ; R192_Ch3.2@5046,5837.22 5008.38,5837.22 4995.7,5824.54 R62_Ch3.2@4961.62,5824.54
HTV_2.5V_Ch4: C46_Ch4.2 R61_Ch4.1 R62_Ch4.2 R192_Ch4.2 U9_Ch4.3 | length 322.5
  Top Layer w15: U9_Ch4.3@6524.28,5798.31 v2(6573.85,5798.31)
  Bottom Layer w15: R61_Ch4.1@6523.62,5873.46 R62_Ch4.2@6523.62,5824.46 ; v2(6573.85,5798.31) 6573.85,5775.85 6564.35,5766.35 C46_Ch4.2@6524.28,5766.35 6524.28,5823.8 R62_Ch4.2@6523.62,5824.46 ; R192_Ch4.2@6608,5837.14 6570.38,5837.14 6557.7,5824.46 R62_Ch4.2@6523.62,5824.46
HTV_2.5V_Ch5: C46_Ch5.2 R61_Ch5.1 R62_Ch5.2 R192_Ch5.2 U9_Ch5.3 | length 322.5
  Top Layer w15: U9_Ch5.3@8479.98,5798.24 v2(8529.55,5798.24)
  Bottom Layer w15: R61_Ch5.1@8479.32,5873.39 R62_Ch5.2@8479.32,5824.39 ; v2(8529.55,5798.24) 8529.55,5775.85 8519.98,5766.28 C46_Ch5.2@8479.98,5766.28 8479.98,5823.72 R62_Ch5.2@8479.32,5824.39 ; R192_Ch5.2@8563.7,5837.06 8526.08,5837.06 8513.4,5824.39 R62_Ch5.2@8479.32,5824.39
HTV_2.5V_Ch6: C46_Ch6.2 R61_Ch6.1 R62_Ch6.2 R192_Ch6.2 U9_Ch6.3 | length 322
  Top Layer w15: U9_Ch6.3@10041.98,5798.16 v2(10091.55,5798.16)
  Bottom Layer w15: R61_Ch6.1@10041.32,5873.31 R62_Ch6.2@10041.32,5824.31 ; v2(10091.55,5798.16) 10091.55,5776.55 10081.2,5766.2 C46_Ch6.2@10041.98,5766.2 10041.98,5823.65 R62_Ch6.2@10041.32,5824.31 ; R192_Ch6.2@10125.7,5836.98 10088.08,5836.98 10075.4,5824.31 R62_Ch6.2@10041.32,5824.31
HTV_2.5V_Ch7: C46_Ch7.2 R61_Ch7.1 R62_Ch7.2 R192_Ch7.2 U9_Ch7.3 | length 319.7
  Top Layer w15: U9_Ch7.3@11603.98,5798.08 v2(11653.55,5798.08)
  Bottom Layer w15: R61_Ch7.1@11603.32,5873.23 R62_Ch7.2@11603.32,5824.23 ; v2(11653.55,5798.08) 11653.55,5780.55 11639.12,5766.12 C46_Ch7.2@11603.98,5766.12 11603.98,5823.57 R62_Ch7.2@11603.32,5824.23 ; R192_Ch7.2@11687.7,5836.91 11650.08,5836.91 11637.4,5824.23 R62_Ch7.2@11603.32,5824.23
HTV_2.5V_Ch8: C46_Ch8.2 R61_Ch8.1 R62_Ch8.2 R192_Ch8.2 U9_Ch8.3 | length 322.5
  Top Layer w15: U9_Ch8.3@13165.98,5798 v2(13215.55,5798)
  Bottom Layer w15: R61_Ch8.1@13165.32,5873.15 R62_Ch8.2@13165.32,5824.15 ; v2(13215.55,5798) 13215.55,5775.55 13206.04,5766.04 C46_Ch8.2@13165.98,5766.04 13165.98,5823.49 R62_Ch8.2@13165.32,5824.15 ; R192_Ch8.2@13249.7,5836.83 13212.08,5836.83 13199.4,5824.15 R62_Ch8.2@13165.32,5824.15
Interrupt1: R69_Ch1.1 R167.1 U2_Ch1.1 U9_Ch1.1 U9_Ch1.7 U24_Ch1.1 | length 12782
  Top Layer w15: v2(1571.15,5748.55) U9_Ch1.7@1623.72,5748.55 ; U9_Ch1.1@1838.28,5698.55 v2(1887.85,5698.55)
  Signal Layer 1 w10: v2(1571.15,5748.55) 1653.45,5748.55 1820,5582 1820,5336 1739.92,5255.92 1739.92,4967.92 1666,4894 1666,3919 1782.8,3802.2 v2(1782.8,3707) 1930.23,3707 v2(1973.18,3664.05)
  Bottom Layer w10: v2(1571.15,5748.55) 1475,5652.4 1475,5011.57 1608.57,4878 7705,4878 7833,5006 7833,6582 8427,7176 R167.1@8427,7246
  Bottom Layer w15: v2(1571.15,5748.55) 1571.6,5749 R69_Ch1.1@1628,5749 1696,5749 1746.45,5698.55 v2(1887.85,5698.55) ; U2_Ch1.1@1718.29,3706.59 1782.39,3706.59 v2(1782.8,3707) ; U24_Ch1.1@1973.18,3629.04 v2(1973.18,3664.05)
Interrupt2: R69_Ch2.1 R166.1 U2_Ch2.1 U9_Ch2.1 U9_Ch2.7 U24_Ch2.1 | length 11203.1
  Top Layer w15: v2(3133.15,5748.47) U9_Ch2.7@3185.72,5748.47 ; U9_Ch2.1@3400.28,5698.47 v2(3449.85,5698.47)
  Signal Layer 1 w10: v2(3133.15,5748.47) 3223.53,5748.47 3389,5583 3389,5336.92 3305.74,5253.66 3305.74,4993.66 3228,4915.92 3228,3918.92 3344.8,3802.13 v2(3344.8,3706.92) 3492.23,3706.92 v2(3535.18,3663.97)
  Bottom Layer w10: v2@3132.7,5748.02 3026,5641.32 3026,4981 3113,4894 7675.61,4894 7796,5014.39 7796,6585 8377.9,7166.9 R166.1@8377.9,7246
  Bottom Layer w15: v2@3132.7,5748.02 v2(3133.15,5748.47) R69_Ch2.1@3189.55,5748.47 3257.55,5748.47 3308,5698.02 v2@3449.4,5698.02 ; U2_Ch2.1@3280.29,3706.51 3344.39,3706.51 v2(3344.8,3706.92) ; U24_Ch2.1@3535.18,3628.96 v2(3535.18,3663.97)
Interrupt3: R69_Ch3.1 R165.1 U2_Ch3.1 U9_Ch3.1 U9_Ch3.7 U24_Ch3.1 | length 9540.7
  Top Layer w15: v2(4695.15,5748.39) U9_Ch3.7@4747.72,5748.39 ; U9_Ch3.1@4962.28,5698.39 v2(5011.85,5698.39)
  Signal Layer 1 w10: v2(4695.15,5748.39) 4781.61,5748.39 4951,5579 4951,5336.84 4867.08,5252.92 4867.08,4996.08 4790,4919 4790,3918.84 4906.8,3802.05 v2(4906.8,3706.84) 5054.23,3706.84 v2(5097.18,3663.89)
  Bottom Layer w10: v2@4694.7,5747.94 4613,5666.24 4613,4986 4689,4910 7647,4910 7764.25,5027.25 7764.25,6588.25 8328.8,7152.8 R165.1@8328.8,7246
  Bottom Layer w15: v2@4694.7,5747.94 v2(4695.15,5748.39) R69_Ch3.1@4751.55,5748.39 4819.55,5748.39 4870,5697.94 v2@5011.4,5697.94 ; U2_Ch3.1@4842.29,3706.43 4906.39,3706.43 v2(4906.8,3706.84) ; U24_Ch3.1@5097.18,3628.88 v2(5097.18,3663.89)
Interrupt4: R69_Ch4.1 R164.1 U2_Ch4.1 U9_Ch4.1 U9_Ch4.7 U24_Ch4.1 | length 7918.3
  Top Layer w15: v2(6257.15,5748.31) U9_Ch4.7@6309.72,5748.31 ; U9_Ch4.1@6524.28,5698.31 v2(6573.85,5698.31)
  Signal Layer 1 w10: v2(6257.15,5748.31) 6335.69,5748.31 6501,5583 6501,5324.76 6426.06,5249.83 6426.06,4997.06 6352,4923 6352,3918.76 6468.8,3801.97 v2(6468.8,3706.76) 6616.23,3706.76 v2(6659.18,3663.81)
  Bottom Layer w10: v2@6256.7,5747.87 6160,5651.17 6160,5006 6240,4926 7626,4926 7728,5028 7728,6658 8279.7,7209.7 R164.1@8279.7,7246
  Bottom Layer w15: v2@6256.7,5747.87 v2(6257.15,5748.31) R69_Ch4.1@6313.55,5748.31 6381.55,5748.31 6432,5697.87 v2@6573.4,5697.87 ; U2_Ch4.1@6404.29,3706.35 6468.39,3706.35 v2(6468.8,3706.76) ; U24_Ch4.1@6659.18,3628.8 v2(6659.18,3663.81)
Interrupt5: R69_Ch5.1 R171.1 U2_Ch5.1 U9_Ch5.1 U9_Ch5.7 U24_Ch5.1 | length 5004.8
  Top Layer w15: v2(8212.85,5748.24) U9_Ch5.7@8265.42,5748.24 ; U9_Ch5.1@8479.98,5698.24 v2(8529.55,5698.24)
  Signal Layer 1 w10: v2(8212.85,5748.24) 8297.76,5748.24 8454,5592 8454,5321.98 8382,5249.98 8382,4964.3 8307.7,4890 8307.7,3918.69 8424.5,3801.89 v2(8424.5,3706.69) 8571.93,3706.69 v2(8614.88,3663.73)
  Bottom Layer w10: v2@8212.4,5747.79 8071.26,5747.79 7964,5855.05 7964,6549 8623.4,7208.4 R171.1@8623.4,7246
  Bottom Layer w15: v2@8212.4,5747.79 v2(8212.85,5748.24) R69_Ch5.1@8269.25,5748.24 8337.25,5748.24 8387.7,5697.79 v2@8529.1,5697.79 ; U2_Ch5.1@8359.99,3706.28 8424.09,3706.28 v2(8424.5,3706.69) ; U24_Ch5.1@8614.88,3628.72 v2(8614.88,3663.73)
Interrupt6: R69_Ch6.1 R170.1 U2_Ch6.1 U9_Ch6.1 U9_Ch6.7 U24_Ch6.1 | length 8155.2
  Top Layer w15: v2(9774.85,5748.16) U9_Ch6.7@9827.42,5748.16 ; U9_Ch6.1@10041.98,5698.16 v2(10091.55,5698.16)
  Signal Layer 1 w10: v2(9774.85,5748.16) 9777.01,5746 9859.7,5746 10019,5586.7 10019,5324.91 9944,5249.91 9944,4979 9869.7,4904.7 9869.7,3918.61 9986.5,3801.81 v2(9986.5,3706.61) 10133.93,3706.61 v2(10176.88,3663.65)
  Bottom Layer w10: R170.1@8574.3,7246 8574.3,7203.22 7926,6554.92 7926,5021 8033,4914 9580,4914 9674,5008 9674,5647.31 v2@9774.4,5747.71
  Bottom Layer w15: v2@9774.4,5747.71 v2(9774.85,5748.16) R69_Ch6.1@9831.25,5748.16 9899.25,5748.16 9949.7,5697.71 v2@10091.1,5697.71 ; U2_Ch6.1@9921.99,3706.2 9986.09,3706.2 v2(9986.5,3706.61) ; U24_Ch6.1@10176.88,3628.64 v2(10176.88,3663.65)
Interrupt7: R69_Ch7.1 R169.1 U2_Ch7.1 U9_Ch7.1 U9_Ch7.7 U24_Ch7.1 | length 9762.2
  Top Layer w15: v2(11336.85,5748.08) U9_Ch7.7@11389.42,5748.08 ; U9_Ch7.1@11603.98,5698.08 v2(11653.55,5698.08)
  Signal Layer 1 w10: v2(11336.85,5748.08) 11408.92,5748.08 11577,5580 11577,5327 11506,5256 11506,4986 11431.7,4911.7 11431.7,3918.53 11548.5,3801.73 v2(11548.5,3706.53) 11695.93,3706.53 v2(11738.88,3663.57)
  Bottom Layer w10: R169.1@8525.2,7246 8525.2,7199.2 7894,6568 7894,5018 8014,4898 11151,4898 11228.82,4975.82 11228.82,5640.04 v2@11336.4,5747.63
  Bottom Layer w15: v2@11336.4,5747.63 v2(11336.85,5748.08) R69_Ch7.1@11393.25,5748.08 11461.25,5748.08 11511.7,5697.63 v2@11653.1,5697.63 ; U2_Ch7.1@11483.99,3706.12 11548.09,3706.12 v2(11548.5,3706.53) ; U24_Ch7.1@11738.88,3628.56 v2(11738.88,3663.57)
Interrupt8: R69_Ch8.1 R168.1 U2_Ch8.1 U9_Ch8.1 U9_Ch8.7 U24_Ch8.1 | length 11344.2
  Top Layer w15: v2(12898.85,5748) U9_Ch8.7@12951.42,5748 ; U9_Ch8.1@13165.98,5698 v2(13215.55,5698)
  Signal Layer 1 w10: v2(12898.85,5748) 12980,5748 13139,5589 13139,5320.75 13065.25,5247 13065.25,4962.55 12993.7,4891 12993.7,3918.45 13110.5,3801.65 v2(13110.5,3706.45) 13257.93,3706.45 v2(13300.88,3663.49)
  Bottom Layer w10: R168.1@8476.1,7246 8476.1,7185.69 7866,6575.59 7866,5012.38 7996.38,4882 12660,4882 12771,4993 12771,5620.15 v2(12898.85,5748)
  Bottom Layer w15: v2(12898.85,5748) 12899.3,5748.45 R69_Ch8.1@12955.7,5748.45 13023.7,5748.45 13074.15,5698 v2(13215.55,5698) ; U2_Ch8.1@13045.99,3706.04 13110.09,3706.04 v2(13110.5,3706.45) ; U24_Ch8.1@13300.88,3628.49 v2(13300.88,3663.49)
IoutN1: C28_Ch1.2 R40_Ch1.2 R91.1 TP8_Ch1.1 | length 463.9
  Top Layer w10: R40_Ch1.2@3679.5,7355.63 3694,7370.13 3722.88,7370.13 C28_Ch1.2@3744.87,7348.14 ; C28_Ch1.2@3744.87,7348.7 3766.37,7370.19 3842.53,7370.19 ; TP8_Ch1.1@3842.53,7314.19 3842.53,7370.19 ; R91.1@4023.49,7273.89 4009.4,7287.98 3968.54,7287.98 3886.33,7370.19 3842.53,7370.19
IoutN2: C28_Ch2.2 R40_Ch2.2 R96.1 TP8_Ch2.1 | length 591
  Top Layer w10: R40_Ch2.2@4010.75,6583.67 3996.25,6598.17 3996.25,6627.05 C28_Ch2.2@4018.25,6649.05 3996.75,6670.54 3996.75,6746.7 ; TP8_Ch2.1@4052.75,6746.7 3996.75,6746.7 ; R96.1@4230.56,6901.77 4216.56,6887.77 4216.56,6854.86 4189.4,6827.7 4025.38,6827.7 3996.75,6799.07 3996.75,6746.7
IoutN3: C28_Ch3.2 R40_Ch3.2 R103.1 TP8_Ch3.1 | length 434
  Top Layer w10: R103.1@4455.74,6901.77 4441.65,6887.68 4441.65,6855.63 4516.61,6780.67 4516.61,6670.54 C28_Ch3.2@4538.11,6649.05 4516.11,6627.05 4516.11,6598.17 R40_Ch3.2@4530.61,6583.67 ; 4517.61,6746.7 TP8_Ch3.1@4572.61,6746.7
IoutN4: C28_Ch4.2 R40_Ch4.2 R113.1 TP8_Ch4.1 | length 463.9
  Top Layer w10: R113.1@4729.8,7216.33 4743.89,7202.24 4784.75,7202.24 4866.97,7120.03 4910.76,7120.03 ; TP8_Ch4.1@4910.76,7176.03 4910.76,7120.03 ; R40_Ch4.2@5073.8,7134.03 5059.3,7119.53 5030.41,7119.53 C28_Ch4.2@5008.42,7141.52 4986.92,7120.03 4910.76,7120.03
IoutN5: C28_Ch5.2 R40_Ch5.2 R122.1 TP8_Ch5.1 | length 463.9
  Top Layer w10: R40_Ch5.2@10321.2,7355.32 10335.7,7369.82 10364.58,7369.82 C28_Ch5.2@10386.58,7347.82 ; C28_Ch5.2@10386.58,7348.38 10408.07,7369.88 10484.23,7369.88 ; TP8_Ch5.1@10484.23,7313.88 10484.23,7369.88 ; R122.1@10665.19,7273.57 10651.1,7287.67 10610.24,7287.67 10528.03,7369.88 10484.23,7369.88
IoutN6: C28_Ch6.2 R40_Ch6.2 R127.1 TP8_Ch6.1 | length 591
  Top Layer w10: R40_Ch6.2@10652.45,6583.35 10637.95,6597.85 10637.95,6626.74 C28_Ch6.2@10659.95,6648.73 10638.45,6670.23 10638.45,6746.39 ; TP8_Ch6.1@10694.45,6746.39 10638.45,6746.39 ; R127.1@10872.26,6901.45 10858.26,6887.45 10858.26,6854.54 10831.1,6827.39 10667.08,6827.39 10638.45,6798.76 10638.45,6746.39
IoutN7: C28_Ch7.2 R40_Ch7.2 R134.1 TP8_Ch7.1 | length 434
  Top Layer w10: R134.1@11097.44,6901.45 11083.35,6887.36 11083.35,6855.32 11158.31,6780.35 11158.31,6670.23 C28_Ch7.2@11179.81,6648.73 11157.81,6626.74 11157.81,6597.85 R40_Ch7.2@11172.31,6583.35 ; 11159.31,6746.39 TP8_Ch7.1@11214.31,6746.39
IoutN8: C28_Ch8.2 R40_Ch8.2 R144.1 TP8_Ch8.1 | length 463.9
  Top Layer w10: R144.1@11371.5,7216.02 11385.59,7201.93 11426.45,7201.93 11508.67,7119.71 11552.47,7119.71 ; TP8_Ch8.1@11552.47,7175.71 11552.47,7119.71 ; R40_Ch8.2@11715.5,7133.71 11701,7119.21 11672.11,7119.21 C28_Ch8.2@11650.12,7141.21 11628.62,7119.71 11552.47,7119.71
IoutP1: C28_Ch1.1 D12.2 R36_Ch1.2 R90.1 R186_Ch1.2 R245.1 TP7_Ch1.1 U13.1 | length 5487.5
  Top Layer w10: R36_Ch1.2@3679.5,7404.63 3694,7390.13 3723.88,7390.13 C28_Ch1.1@3744.87,7411.13 ; C28_Ch1.1@3744.87,7411.69 3766.37,7390.19 3842,7390.19 ; TP7_Ch1.1@3842.53,7446.19 TP7_Ch1.1@3842.53,7445.63 3842.53,7390.72 3842,7390.19 ; R90.1@4023.49,7322.07 4009.4,7307.98 3976.82,7307.98 3894.61,7390.19 3842,7390.19 ; v2(5792,7311) 5832.52,7311 R245.1@5837.25,7315.72
  Signal Layer 1 w10: TP7_Ch1.1@3842.53,7445.63 4173.16,7115 5596,7115 v2(5792,7311)
  Bottom Layer w12: R186_Ch1.2@2107,6175 2107,6223.7 3328.93,7445.63 3708.63,7445.63 D12.2@3710,7447 3841.16,7447 TP7_Ch1.1@3842.53,7445.63 4069,7219.16 4069,7074.7 4055.6,7061.3 U13.1@4021.87,7061.3
IoutP2: C28_Ch2.1 D19.2 R36_Ch2.2 R94.1 R186_Ch2.2 R246.1 TP7_Ch2.1 U13.5 | length 3894.6
  Top Layer w10: TP7_Ch2.1@3920.75,6746.7 3975.75,6746.7 ; R36_Ch2.2@3961.75,6583.67 3976.25,6598.17 3976.25,6628.05 C28_Ch2.1@3955.25,6649.05 3976.75,6670.54 3976.75,6807.36 4017.09,6847.7 4181.11,6847.7 4196.56,6863.14 4196.56,6887.77 R94.1@4182.56,6901.77 ; v2(5673,7061) 5887.06,7275.06 R246.1@5887.06,7315.72
  Signal Layer 1 w10: TP7_Ch2.1@3920.75,6746.7 4154.05,6980 5592,6980 v2(5673,7061)
  Bottom Layer w12: R186_Ch2.2@3670,6173.92 3670,6242 3922.12,6494.12 D19.2@3922.12,6614.17 3920.75,6615.54 TP7_Ch2.1@3920.75,6746.7 4130.13,6956.08 U13.5@4130.13,7061.3
IoutP3: C28_Ch3.1 D21.2 R36_Ch3.2 R101.1 R186_Ch3.2 R249.1 TP7_Ch3.1 U14.5 | length 3892.7
  Top Layer w10: R101.1@4407.56,6901.77 4421.65,6887.68 4421.65,6847.35 4496.61,6772.38 4496.61,6746.7 ; TP7_Ch3.1@4440.61,6746.7 4496.61,6746.7 ; R36_Ch3.2@4481.61,6583.67 4496.11,6598.17 4496.11,6628.05 C28_Ch3.1@4475.12,6649.05 4496.61,6670.54 4496.61,6746.7 ; v2@5717,7037 5936.87,7256.87 R249.1@5936.87,7315.72
  Signal Layer 1 w10: TP7_Ch3.1@4440.61,6746.7 4645.91,6952 5634,6952 v2(5717,7035)
  Bottom Layer w12: U14.5@4623.16,7136.1 4580.69,7136.1 4536.29,7091.7 4536.29,6842.38 TP7_Ch3.1@4440.61,6746.7 D21.2@4440.61,6615.54 4440.61,6506.39 4573.3,6373.7 5088.7,6373.7 5232,6230.4 R186_Ch3.2@5232,6173.84
IoutP4: C28_Ch4.1 D23.2 R36_Ch4.2 R111.1 R186_Ch4.2 R250.1 TP7_Ch4.1 U14.1 | length 4218.8
  Top Layer w10: R111.1@4729.8,7168.15 4743.89,7182.24 4776.47,7182.24 4858.68,7100.03 4911.29,7100.03 ; TP7_Ch4.1@4910.76,7044.03 4910.76,7099.5 4911.29,7100.03 ; R36_Ch4.2@5073.8,7085.03 5059.3,7099.53 5029.41,7099.53 C28_Ch4.1@5008.42,7078.53 4986.92,7100.03 4911.29,7100.03 ; v2(5820,7096) 5986.68,7262.68 R250.1@5986.68,7315.72
  Signal Layer 1 w10: TP7_Ch4.1@4910.76,7044.03 5588.03,7044.03 5639.13,7095.13 5819.13,7095.13 v2(5820,7096)
  Bottom Layer w12: U14.1@4731.43,7136.1 4818.69,7136.1 TP7_Ch4.1@4910.76,7044.03 D23.2@5041.93,7044.03 5328.97,7044.03 5905,6468 6626.7,6468 6794,6300.7 R186_Ch4.2@6794,6173.76
IoutP5: C28_Ch5.1 D25.2 R36_Ch5.2 R121.1 R186_Ch5.2 R253.1 TP7_Ch5.1 U17.1 | length 8006.7
  Top Layer w10: R253.1@6153.68,7315.72 6153.68,7077.32 v2(6169,7062) ; R36_Ch5.2@10321.2,7404.32 10335.7,7389.82 10365.58,7389.82 C28_Ch5.1@10386.58,7410.82 ; C28_Ch5.1@10386.58,7411.37 10408.07,7389.88 10483.7,7389.88 ; TP7_Ch5.1@10484.23,7445.88 TP7_Ch5.1@10484.23,7445.32 10484.23,7390.41 10483.7,7389.88 ; R121.1@10665.19,7321.76 10651.1,7307.67 10618.52,7307.67 10536.31,7389.88 10483.7,7389.88
  Signal Layer 1 w10: v2(6169,7062) 10100.91,7062 TP7_Ch5.1@10484.23,7445.32
  Bottom Layer w12: R186_Ch5.2@8749.7,6173.69 8749.7,6222.39 9971.63,7444.32 10351.33,7444.32 D25.2@10352.7,7445.69 10483.86,7445.69 TP7_Ch5.1@10484.23,7445.32 10711.7,7217.85 10711.7,7073.39 10698.3,7059.98 U17.1@10664.57,7059.98
IoutP6: C28_Ch6.1 D27.2 R36_Ch6.2 R125.1 R186_Ch6.2 R254.1 TP7_Ch6.1 U17.5 | length 6440.9
  Top Layer w10: R254.1@6203.68,7315.72 6203.68,7012.52 v2(6242.1,6974.1) ; TP7_Ch6.1@10562.45,6746.39 10617.45,6746.39 ; R36_Ch6.2@10603.45,6583.35 10617.95,6597.85 10617.95,6627.74 10601.95,6643.73 C28_Ch6.1@10596.95,6648.73 10618.45,6670.23 10618.45,6807.04 10658.79,6847.39 10822.82,6847.39 10838.26,6862.83 10838.26,6887.45 R125.1@10824.26,6901.45
  Signal Layer 1 w10: v2(6242.1,6974.1) 10073.59,6974.11 10173.7,6874 10434.84,6874 TP7_Ch6.1@10562.45,6746.39
  Bottom Layer w12: R186_Ch6.2@10311.7,6173.61 10311.7,6241.69 10563.82,6493.8 D27.2@10563.82,6613.86 10562.45,6615.22 TP7_Ch6.1@10562.45,6746.39 10771.83,6955.77 U17.5@10771.83,7060.98
IoutP7: C28_Ch7.1 D29.2 R36_Ch7.2 R132.1 R186_Ch7.2 R257.1 TP7_Ch7.1 U18.5 | length 7351.3
  Top Layer w10: R257.1@6253.68,7315.72 6253.68,7042.94 v2(6297.63,6998.99) ; R132.1@11049.26,6901.45 11063.35,6887.36 11063.35,6847.03 11138.31,6772.07 11138.31,6746.39 ; TP7_Ch7.1@11082.31,6746.39 11138.31,6746.39 ; R36_Ch7.2@11123.31,6583.35 11137.81,6597.85 11137.81,6627.74 11121.82,6643.73 C28_Ch7.1@11116.82,6648.73 11138.31,6670.23 11138.31,6746.39
  Signal Layer 1 w10: v2@6297.64,6999 10093.7,6999 10191.7,6901 10927.7,6901 TP7_Ch7.1@11082.31,6746.39
  Bottom Layer w12: U18.5@11264.86,7135.79 11222.4,7135.79 11177.99,7091.39 11177.99,6842.07 TP7_Ch7.1@11082.31,6746.39 D29.2@11082.31,6615.22 11082.31,6506.07 11215,6373.39 11730.4,6373.39 11873.7,6230.09 R186_Ch7.2@11873.7,6173.53
IoutP8: C28_Ch8.1 D31.2 R36_Ch8.2 R142.1 R186_Ch8.2 R258.1 TP7_Ch8.1 U18.1 | length 8599.4
  Top Layer w10: R258.1@6303.68,7315.72 6303.68,7073.32 v2@6345,7032 ; R142.1@11371.5,7167.83 11385.59,7181.93 11418.17,7181.93 11500.38,7099.71 11552.99,7099.71 ; TP7_Ch8.1@11552.47,7043.71 11552.47,7099.18 11552.99,7099.71 ; R36_Ch8.2@11715.5,7084.71 11701,7099.21 11671.11,7099.21 C28_Ch8.1@11650.12,7078.22 11628.62,7099.71 11552.99,7099.71
  Signal Layer 1 w10: v2@6345,7032 10101.7,7032 10206.7,6927 11435.75,6927 TP7_Ch8.1@11552.47,7043.71
  Bottom Layer w12: U18.1@11373.13,7135.79 11460.39,7135.79 TP7_Ch8.1@11552.47,7043.71 D31.2@11683.63,7043.71 11970.67,7043.71 12546.7,6467.69 13268.4,6467.69 13435.7,6300.39 R186_Ch8.2@13435.7,6173.45
  other v2: 6344.99,7031.99
L-Drive_Ch1: D4_Ch1.1 R21_Ch1.2 U1_Ch1.5 | length 152.8
  Top Layer w15: U1_Ch1.5@1748.37,3545.79 1748.37,3458.72 D4_Ch1.1@1745.77,3456.11 1745.77,3403.38 R21_Ch1.2@1752.36,3396.78
L-Drive_Ch2: D4_Ch2.1 R21_Ch2.2 U1_Ch2.5 | length 152.8
  Top Layer w15: U1_Ch2.5@3310.37,3545.71 3310.37,3458.64 D4_Ch2.1@3307.77,3456.04 3307.77,3403.3 R21_Ch2.2@3314.36,3396.71
L-Drive_Ch3: D4_Ch3.1 R21_Ch3.2 U1_Ch3.5 | length 152.8
  Top Layer w15: U1_Ch3.5@4872.37,3545.63 4872.37,3458.56 D4_Ch3.1@4869.77,3455.96 4869.77,3403.22 R21_Ch3.2@4876.36,3396.63
L-Drive_Ch4: D4_Ch4.1 R21_Ch4.2 U1_Ch4.5 | length 152.8
  Top Layer w15: U1_Ch4.5@6434.37,3545.55 6434.37,3458.48 D4_Ch4.1@6431.77,3455.88 6431.77,3403.15 R21_Ch4.2@6438.36,3396.55
L-Drive_Ch5: D4_Ch5.1 R21_Ch5.2 U1_Ch5.5 | length 152.8
  Top Layer w15: U1_Ch5.5@8390.07,3545.47 8390.07,3458.4 8387.47,3455.8 8387.47,3403.07 R21_Ch5.2@8394.06,3396.47
L-Drive_Ch6: D4_Ch6.1 R21_Ch6.2 U1_Ch6.5 | length 152.8
  Top Layer w15: U1_Ch6.5@9952.07,3545.39 9952.07,3458.32 D4_Ch6.1@9949.47,3455.73 9949.47,3402.99 R21_Ch6.2@9956.06,3396.39
L-Drive_Ch7: D4_Ch7.1 R21_Ch7.2 U1_Ch7.5 | length 152.8
  Top Layer w15: U1_Ch7.5@11514.07,3545.31 11514.07,3458.25 D4_Ch7.1@11511.47,3455.65 11511.47,3402.91 R21_Ch7.2@11518.06,3396.31
L-Drive_Ch8: D4_Ch8.1 R21_Ch8.2 U1_Ch8.5 | length 152.8
  Top Layer w15: U1_Ch8.5@13076.07,3545.23 13076.07,3458.17 D4_Ch8.1@13073.47,3455.57 13073.47,3402.83 R21_Ch8.2@13080.06,3396.23
LDrive_Ch1: Q7_Ch1.4 R21_Ch1.1 R24_Ch1.2 R25_Ch1.2 | length 1257.7
  Top Layer w15: v2(1629.36,3279.64) R24_Ch1.2@1629.36,3327.6 R25_Ch1.2@1690.83,3327.6 R21_Ch1.1@1752.36,3327.6 ; v1(2449.05,3535.08) Q7_Ch1.4@2497,3535.08
  Signal Layer 2 w15: v2(1629.36,3279.64) 1780.36,3279.64 1845,3215 2231,3215 2413,3397 2413,3499.03 v1(2449.05,3535.08)
LDrive_Ch2: Q7_Ch2.4 R21_Ch2.1 R24_Ch2.2 R25_Ch2.2 | length 1257.7
  Top Layer w15: v2(3191.36,3279.56) R24_Ch2.2@3191.36,3327.52 R25_Ch2.2@3252.83,3327.52 R21_Ch2.1@3314.36,3327.52 ; v1(4011.05,3535) Q7_Ch2.4@4059,3535
  Signal Layer 2 w15: v2(3191.36,3279.56) 3342.36,3279.56 3407,3214.92 3793,3214.92 3975,3396.92 3975,3498.95 v1(4011.05,3535)
LDrive_Ch3: Q7_Ch3.4 R21_Ch3.1 R24_Ch3.2 R25_Ch3.2 | length 1257.7
  Top Layer w15: v2(4753.36,3279.48) R24_Ch3.2@4753.36,3327.44 R25_Ch3.2@4814.83,3327.44 R21_Ch3.1@4876.36,3327.44 ; v1(5573.05,3534.92) Q7_Ch3.4@5621,3534.92
  Signal Layer 2 w15: v2(4753.36,3279.48) 4904.36,3279.48 4969,3214.84 5355,3214.84 5537,3396.84 5537,3498.88 v1(5573.05,3534.92)
LDrive_Ch4: Q7_Ch4.4 R21_Ch4.1 R24_Ch4.2 R25_Ch4.2 | length 1257.7
  Top Layer w15: v2(6315.36,3279.41) R24_Ch4.2@6315.36,3327.36 R25_Ch4.2@6376.83,3327.36 R21_Ch4.1@6438.36,3327.36 ; v1(7135.05,3534.84) Q7_Ch4.4@7183,3534.84
  Signal Layer 2 w15: v2(6315.36,3279.41) 6466.36,3279.41 6531,3214.76 6917,3214.76 7099,3396.76 7099,3498.8 v1(7135.05,3534.84)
